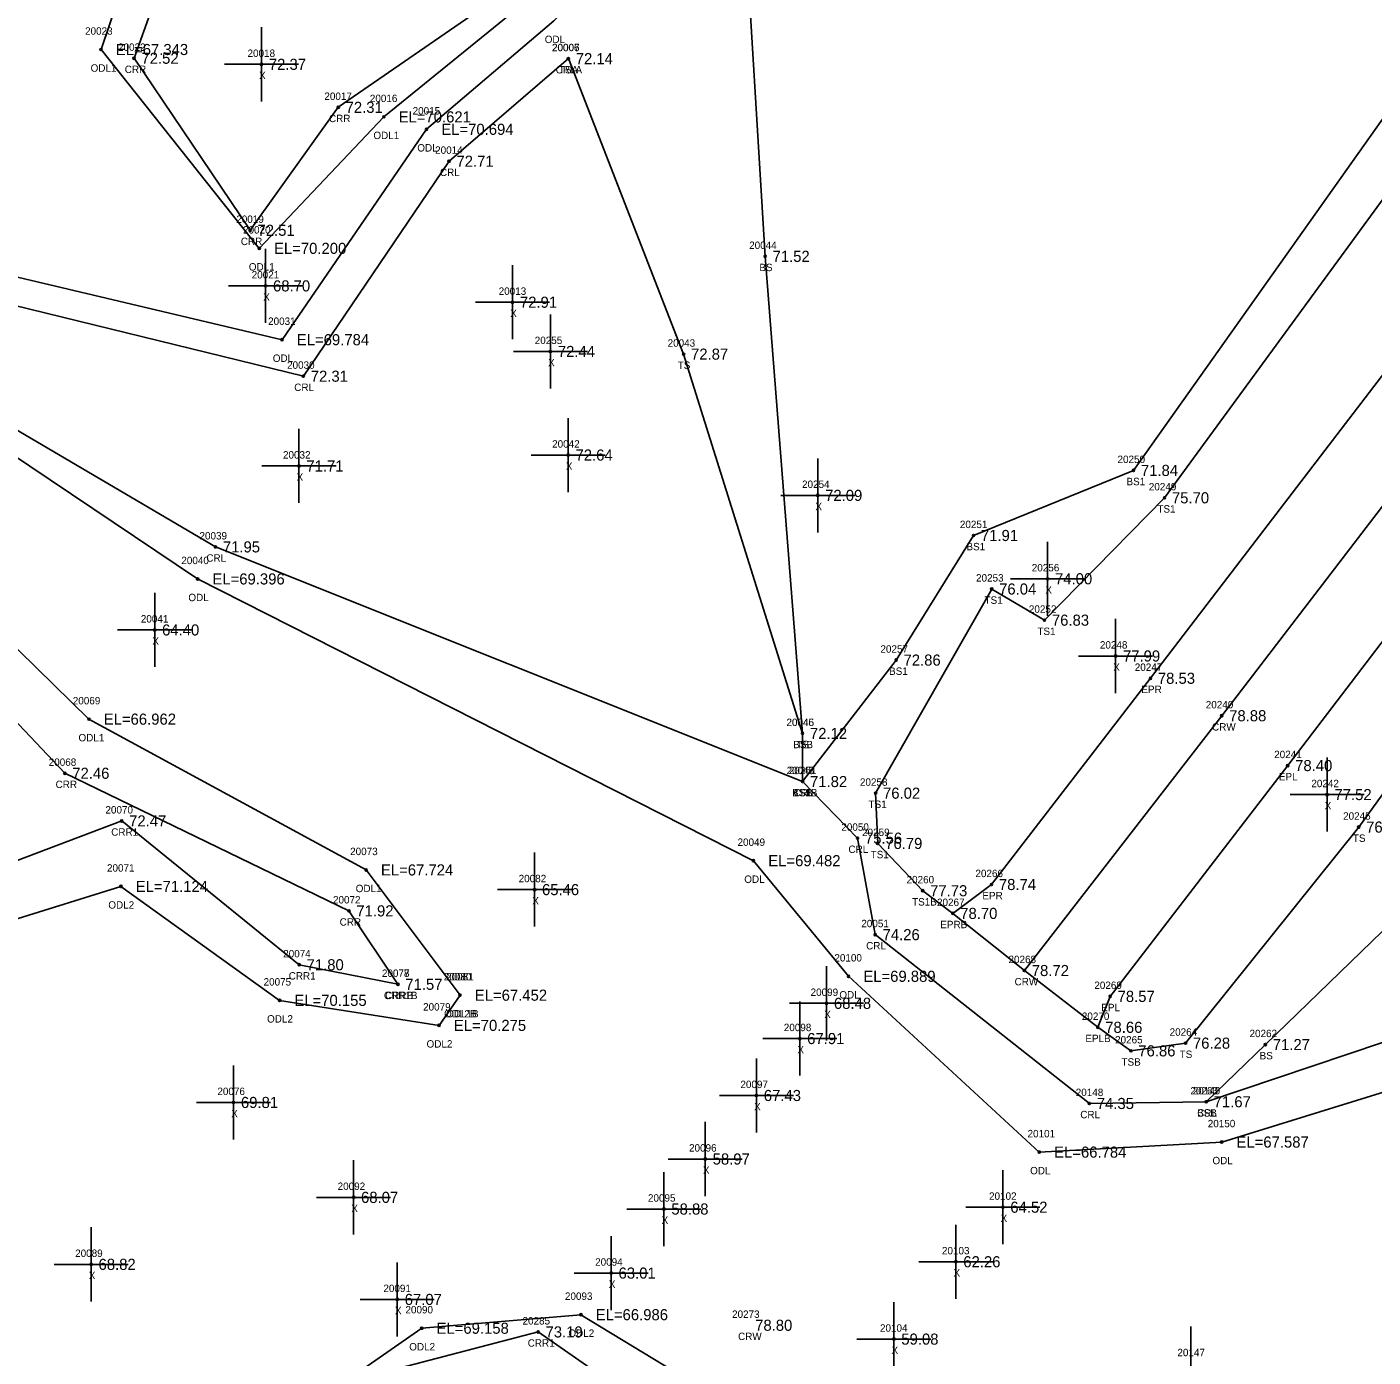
# Model space of a CAD drawing. Extents: x 2505300 to 2506184, y 912965 to 913825.
# Drawn here: x 2505689.1 to 2505870.9, y 913482.7 to 913662.4 of the extents above; entities that cross this region are included whole.
import ezdxf

# ---------------------------------------------------------------- set-up
doc = ezdxf.new("R2010")
doc.units = 0
for name, color, linetype in [('RD_DTM_BkLn1', 7, 'Continuous'), ('RD_DTM_BkLn2', 7, 'Continuous'), ('RD_DTM_BkLn_txCode', 7, 'Continuous'), ('RD_EX_H2O', 7, 'Continuous'), ('RD_EX_H2O_txCode', 7, 'Continuous'), ('RD_EX_Misc', 7, 'Continuous'), ('RD_EX_Misc_txCode', 7, 'Continuous'), ('RD_EX_Road', 7, 'Continuous'), ('RD_EX_Road_txCode', 7, 'Continuous'), ('RD_EX_TX_H2O_ELEV', 7, 'Continuous'), ('RD_EX_TX_Misc_ELEV', 7, 'Continuous'), ('RD_EX_TX_Road_ELEV', 7, 'Continuous'), ('RD_HC_Survey_ELEV', 7, 'Continuous'), ('RD_HC_Survey_txCode', 7, 'Continuous'), ('RD_SMD_Locator', 7, 'Continuous')]:
    doc.layers.add(name, color=color, linetype=linetype)

msp = doc.modelspace()

# ---------------------------------------------------------------- linework, layer by layer
at = {"layer": 'RD_DTM_BkLn1'}
for points in [[(2506032.26, 913807.16), (2505970.46, 913726.68), (2505911.98, 913649.53), (2505850.51, 913569.34), (2505823.85, 913534.92)], [(2505810.12, 913545.7), (2505814.19, 913542.64), (2505823.85, 913534.92), (2505833.77, 913527.25), (2505838.24, 913524.07)]]:
    msp.add_lwpolyline(points, dxfattribs=at)
at = {"layer": 'RD_DTM_BkLn2'}
for points in [[(2506003.2, 913816.23), (2505946.13, 913743.18), (2505885.35, 913668.51), (2505838.59, 913602.48), (2505816.98, 913593.69), (2505806.53, 913576.86), (2505793.9, 913560.45)], [(2506016.9, 913814.52), (2505950.1, 913739.73), (2505890.95, 913664.65), (2505842.78, 913598.78), (2505826.57, 913582.25), (2505819.44, 913586.46), (2505803.76, 913558.88), (2505804.05, 913552.09), (2505810.12, 913545.7)], [(2506050.33, 913797.99), (2506032.99, 913763.99), (2505986.64, 913715.48), (2505928.41, 913636.56), (2505869.01, 913554.3), (2505845.62, 913525.11), (2505838.24, 913524.07)], [(2506063.24, 913729.37), (2506038.62, 913753.69), (2505991.68, 913711.2), (2505934.4, 913631.37), (2505905.82, 913578.23), (2505899.85, 913572.14), (2505876.49, 913544.36), (2505856.4, 913524.92), (2505848.42, 913517.19)], [(2505785.34, 913689.17), (2505788.84, 913631.4), (2505793.89, 913566.95)], [(2505762.26, 913658.11), (2505777.83, 913618.19), (2505793.89, 913566.95), (2505793.9, 913560.45)]]:
    msp.add_lwpolyline(points, dxfattribs=at)
at = {"layer": 'RD_EX_H2O'}
for points in [[(2505785.34, 913689.17), (2505758.38, 913667.37), (2505737.34, 913650.24), (2505720.51, 913632.48), (2505699.15, 913659.34), (2505721.81, 913726.44)], [(2505757.9, 913670.02), (2505731.18, 913651.53), (2505719.28, 913634.92), (2505703.6, 913658.16), (2505725.09, 913718.19)], [(2505785.34, 913689.17), (2505760.31, 913663.21), (2505743.1, 913648.56), (2505723.59, 913620.14), (2505672.59, 913632.18), (2505661.09, 913622.14), (2505712.19, 913587.82), (2505787.26, 913549.76), (2505800.1, 913534.14), (2505825.87, 913510.39), (2505850.5, 913511.75), (2505883.26, 913521.88), (2505912.04, 913531.86), (2505948.81, 913534.96), (2505974.98, 913528.19), (2506003.87, 913517.71), (2506051.32, 913503.49), (2506114.3, 913484.75), (2506121.45, 913493.97), (2506156, 913550.08)], [(2505762.26, 913658.11), (2505746.15, 913644.25), (2505726.47, 913615.21), (2505674.21, 913628.01), (2505666.25, 913620.58), (2505714.6, 913592.15), (2505793.9, 913560.45), (2505801.32, 913552.8), (2505803.7, 913539.77), (2505832.63, 913516.96), (2505848.42, 913517.19), (2505881.86, 913528.44), (2505910.2, 913538.78), (2505939.3, 913544.45), (2505946.25, 913542.54), (2505974.65, 913535.18), (2506004.11, 913524.7), (2506052.03, 913515.47), (2506115.49, 913494.68), (2506138.05, 913548.89)], [(2505582.66, 913526.35), (2505594.25, 913570.52), (2505642.43, 913614.24), (2505650.18, 913615.25), (2505697.51, 913568.88), (2505734.95, 913548.51), (2505747.63, 913531.59)], [(2505594.65, 913525.76), (2505599.08, 913569.22), (2505647.5, 913611.03), (2505694.26, 913561.57), (2505732.63, 913542.98), (2505739.24, 913533.06)], [(2505594.65, 913525.76), (2505643.36, 913532.93), (2505701.94, 913555.13), (2505725.91, 913535.7), (2505739.24, 913533.06)], [(2505582.66, 913526.35), (2505594.35, 913519.76), (2505642.96, 913527.95), (2505701.83, 913546.28), (2505723.26, 913530.89), (2505744.8, 913527.51), (2505747.63, 913531.59)], [(2505660.9, 913411.21), (2505684.62, 913438.72), (2505715.28, 913467.7), (2505742.46, 913486.6), (2505763.96, 913488.43), (2505794.61, 913469.83), (2505812.57, 913467.2), (2505833.64, 913450.28), (2505872.88, 913457.34), (2505893.17, 913479.86), (2505942.46, 913480.08), (2505995.98, 913475.04), (2506045.33, 913460.93), (2506077.87, 913439.29), (2506087.99, 913429.78), (2506108.19, 913381.27)], [(2505789.47, 913464.31), (2505758.18, 913486.1), (2505736.66, 913480.49), (2505719.32, 913463.86), (2505699.9, 913439.21), (2505669.03, 913402.75), (2505628.5, 913357.9), (2505593, 913316.39), (2505556.58, 913279.8), (2505487.72, 913211.38), (2505413.81, 913149.81), (2505341.31, 913072.1)]]:
    msp.add_lwpolyline(points, dxfattribs=at)
at = {"layer": 'RD_EX_Misc'}
for p, q in [((2505720.81, 913652.34), (2505720.81, 913662.34)), ((2505715.81, 913657.34), (2505725.81, 913657.34)), ((2505721.37, 913622.41), (2505721.37, 913632.41)), ((2505754.72, 913620.2), (2505754.72, 913630.2)), ((2505716.37, 913627.41), (2505726.37, 913627.41)), ((2505749.72, 913625.2), (2505759.72, 913625.2)), ((2505759.84, 913613.55), (2505759.84, 913623.55)), ((2505754.84, 913618.55), (2505764.84, 913618.55)), ((2505762.23, 913599.56), (2505762.23, 913609.56)), ((2505725.88, 913598.08), (2505725.88, 913608.08)), ((2505757.23, 913604.56), (2505767.23, 913604.56)), ((2505795.94, 913594.11), (2505795.94, 913604.11)), ((2505720.88, 913603.08), (2505730.88, 913603.08)), ((2505790.94, 913599.11), (2505800.94, 913599.11)), ((2505826.99, 913582.84), (2505826.99, 913592.84)), ((2505821.99, 913587.84), (2505831.99, 913587.84)), ((2505706.39, 913575.93), (2505706.39, 913585.93)), ((2505836.17, 913572.41), (2505836.17, 913582.41)), ((2505701.39, 913580.93), (2505711.39, 913580.93)), ((2505831.17, 913577.41), (2505841.17, 913577.41)), ((2505864.73, 913553.69), (2505864.73, 913563.69)), ((2505859.73, 913558.69), (2505869.73, 913558.69)), ((2505757.7, 913540.85), (2505757.7, 913550.85)), ((2505752.7, 913545.85), (2505762.7, 913545.85)), ((2505797.13, 913525.49), (2505797.13, 913535.49)), ((2505792.13, 913530.49), (2505802.13, 913530.49)), ((2505793.52, 913520.73), (2505793.52, 913530.73)), ((2505788.52, 913525.73), (2505798.52, 913525.73)), ((2505717.04, 913512.1), (2505717.04, 913522.1)), ((2505787.66, 913513.04), (2505787.66, 913523.04)), ((2505712.04, 913517.1), (2505722.04, 913517.1)), ((2505782.66, 913518.04), (2505792.66, 913518.04)), ((2505780.75, 913504.46), (2505780.75, 913514.46)), ((2505733.26, 913499.28), (2505733.26, 913509.28)), ((2505775.75, 913509.46), (2505785.75, 913509.46)), ((2505775.17, 913497.7), (2505775.17, 913507.7)), ((2505820.95, 913497.95), (2505820.95, 913507.95)), ((2505728.26, 913504.28), (2505738.26, 913504.28)), ((2505770.17, 913502.7), (2505780.17, 913502.7)), ((2505815.95, 913502.95), (2505825.95, 913502.95)), ((2505697.81, 913490.23), (2505697.81, 913500.23)), ((2505814.6, 913490.58), (2505814.6, 913500.58)), ((2505768.04, 913489.05), (2505768.04, 913499.05)), ((2505692.81, 913495.23), (2505702.81, 913495.23)), ((2505739.16, 913485.49), (2505739.16, 913495.49)), ((2505809.6, 913495.58), (2505819.6, 913495.58)), ((2505763.04, 913494.05), (2505773.04, 913494.05)), ((2505734.16, 913490.49), (2505744.16, 913490.49)), ((2505806.23, 913480.13), (2505806.23, 913490.13)), ((2505846.35, 913476.82), (2505846.35, 913486.82)), ((2505801.23, 913485.13), (2505811.23, 913485.13))]:
    msp.add_line(p, q, dxfattribs=at)
at = {"layer": 'RD_EX_Road'}
for points in [[(2506024.03, 913813.1), (2505962.01, 913732.06), (2505903.3, 913655.93), (2505840.88, 913574.4), (2505819.41, 913546.54), (2505814.19, 913542.64)], [(2506040.71, 913800.23), (2505979.73, 913720.47), (2505920.44, 913642.61), (2505859.42, 913562.61), (2505835.44, 913531.43), (2505833.77, 913527.25)]]:
    msp.add_lwpolyline(points, dxfattribs=at)
at = {"layer": 'RD_SMD_Locator'}
for centre in [(2505699.15, 913659.34), (2505703.6, 913658.16), (2505720.81, 913657.34), (2505762.26, 913658.11), (2505762.26, 913658.11), (2505731.18, 913651.53), (2505737.34, 913650.24), (2505743.1, 913648.56), (2505746.15, 913644.25), (2505719.28, 913634.92), (2505720.51, 913632.48), (2505788.84, 913631.4), (2505721.37, 913627.41), (2505754.72, 913625.2), (2505723.59, 913620.14), (2505759.84, 913618.55), (2505777.83, 913618.19), (2505726.47, 913615.21), (2505762.23, 913604.56), (2505725.88, 913603.08), (2505838.59, 913602.48), (2505795.94, 913599.11), (2505842.78, 913598.78), (2505816.98, 913593.69), (2505714.6, 913592.15), (2505712.19, 913587.82), (2505826.99, 913587.84), (2505819.44, 913586.46), (2505826.57, 913582.25), (2505706.39, 913580.93), (2505806.53, 913576.86), (2505836.17, 913577.41), (2505840.88, 913574.4), (2505850.51, 913569.34), (2505697.51, 913568.88), (2505793.89, 913566.95), (2505793.89, 913566.95), (2505859.42, 913562.61), (2505694.26, 913561.57), (2505793.9, 913560.45), (2505793.9, 913560.45), (2505793.9, 913560.45), (2505803.76, 913558.88), (2505864.73, 913558.69), (2505701.94, 913555.13), (2505801.32, 913552.8), (2505869.01, 913554.3), (2505804.05, 913552.09), (2505787.26, 913549.76), (2505734.95, 913548.51), (2505701.83, 913546.28), (2505757.7, 913545.85), (2505810.12, 913545.7), (2505819.41, 913546.54), (2505732.63, 913542.98), (2505814.19, 913542.64), (2505803.7, 913539.77), (2505725.91, 913535.7), (2505823.85, 913534.92), (2505739.24, 913533.06), (2505739.24, 913533.06), (2505800.1, 913534.14), (2505747.63, 913531.59), (2505747.63, 913531.59), (2505835.44, 913531.43), (2505723.26, 913530.89), (2505797.13, 913530.49), (2505744.8, 913527.51), (2505793.52, 913525.73), (2505833.77, 913527.25), (2505838.24, 913524.07), (2505845.62, 913525.11), (2505856.4, 913524.92), (2505717.04, 913517.1), (2505787.66, 913518.04), (2505832.63, 913516.96), (2505848.42, 913517.19), (2505848.42, 913517.19), (2505850.5, 913511.75), (2505780.75, 913509.46), (2505825.87, 913510.39), (2505733.26, 913504.28), (2505775.17, 913502.7), (2505820.95, 913502.95), (2505697.81, 913495.23), (2505814.6, 913495.58), (2505768.04, 913494.05), (2505739.16, 913490.49), (2505763.96, 913488.43), (2505742.46, 913486.6), (2505758.18, 913486.1), (2505806.23, 913485.13)]:
    msp.add_circle(centre, 0.15, dxfattribs=at)

# ---------------------------------------------------------------- texts
at = {"layer": 'RD_DTM_BkLn_txCode'}
for s, p in [('20007', (2505760.07, 913659.11)), ('TSA', (2505760.98, 913656.11)), ('20044', (2505786.68, 913632.4)), ('BS', (2505788.06, 913629.4)), ('20043', (2505775.67, 913619.19)), ('TS', (2505777.03, 913616.19)), ('20250', (2505836.43, 913603.48)), ('BS1', (2505837.64, 913600.48)), ('20249', (2505840.66, 913599.78)), ('TS1', (2505841.82, 913596.78)), ('20251', (2505815.14, 913594.69)), ('BS1', (2505816.03, 913591.69)), ('20253', (2505817.32, 913587.46)), ('TS1', (2505818.47, 913584.46)), ('20252', (2505824.46, 913583.25)), ('TS1', (2505825.61, 913580.25)), ('20257', (2505804.41, 913577.86)), ('BS1', (2505805.58, 913574.86)), ('20046', (2505791.71, 913567.95)), ('20045', (2505791.73, 913567.95)), ('BSB', (2505792.63, 913564.95)), ('TS', (2505793.09, 913564.95)), ('20047', (2505791.74, 913561.45)), ('20261', (2505792.04, 913561.45)), ('20258', (2505801.64, 913559.88)), ('BS1B', (2505792.48, 913558.45)), ('TSB', (2505792.63, 913558.45)), ('TS1', (2505802.8, 913556.88)), ('20245', (2505866.9, 913555.3)), ('20259', (2505801.93, 913553.09)), ('TS', (2505868.22, 913552.3)), ('TS1', (2505803.09, 913550.09)), ('20260', (2505807.94, 913546.7)), ('TS1B', (2505808.68, 913543.7)), ('20265', (2505836.1, 913525.07)), ('20264', (2505843.47, 913526.11)), ('20262', (2505854.26, 913525.92)), ('TS', (2505844.82, 913523.11)), ('BS', (2505855.62, 913522.92)), ('TSB', (2505836.97, 913522.07)), ('20263', (2505846.28, 913518.19)), ('BSB', (2505847.17, 913515.19))]:
    msp.add_text(s, height=1, dxfattribs=at).set_placement(p)
at = {"layer": 'RD_EX_H2O_txCode'}
for s, p in [('20023', (2505696.99, 913661.34)), ('20022', (2505701.44, 913659.16)), ('ODL', (2505759.07, 913660.21)), ('20006', (2505760.04, 913659.11)), ('ODL1', (2505697.74, 913656.34)), ('CRR', (2505702.35, 913656.16)), ('CRLA', (2505760.55, 913656.11)), ('20017', (2505729.31, 913652.53)), ('20016', (2505735.45, 913652.24)), ('20015', (2505741.23, 913650.56)), ('CRR', (2505729.93, 913649.53)), ('ODL1', (2505735.93, 913647.24)), ('ODL', (2505741.86, 913645.56)), ('20014', (2505744.27, 913645.25)), ('CRL', (2505744.92, 913642.25)), ('20019', (2505717.41, 913635.92)), ('20020', (2505718.32, 913634.48)), ('CRR', (2505718.03, 913632.92)), ('ODL1', (2505719.1, 913629.48)), ('20031', (2505721.71, 913622.14)), ('ODL', (2505722.34, 913617.14)), ('20030', (2505724.27, 913616.21)), ('CRL', (2505725.24, 913613.21)), ('20039', (2505712.44, 913593.15)), ('CRL', (2505713.37, 913590.15)), ('20040', (2505709.99, 913589.82)), ('ODL', (2505710.94, 913584.82)), ('20069', (2505695.33, 913570.88)), ('ODL1', (2505696.1, 913565.88)), ('20068', (2505692.08, 913562.57)), ('20048', (2505791.74, 913561.45)), ('CRR', (2505693.01, 913559.57)), ('CRL', (2505792.67, 913558.45)), ('20070', (2505699.74, 913556.13)), ('20050', (2505799.13, 913553.8)), ('CRR1', (2505700.52, 913553.13)), ('20073', (2505732.79, 913550.51)), ('20049', (2505785.11, 913551.76)), ('CRL', (2505800.09, 913550.8)), ('20071', (2505699.95, 913548.28)), ('ODL', (2505786.02, 913546.76)), ('ODL1', (2505733.54, 913545.51)), ('ODL2', (2505700.13, 913543.28)), ('20072', (2505730.47, 913543.98)), ('CRR', (2505731.37, 913540.98)), ('20051', (2505801.83, 913540.77)), ('CRL', (2505802.48, 913537.77)), ('20074', (2505723.75, 913536.7)), ('20100', (2505798.19, 913536.14)), ('20077', (2505737.08, 913534.06)), ('20078', (2505737.08, 913534.06)), ('20075', (2505721.1, 913532.89)), ('CRR1', (2505724.49, 913533.7)), ('20080', (2505745.44, 913533.59)), ('20081', (2505745.76, 913533.59)), ('CRR1B', (2505737.35, 913531.06)), ('CRRB', (2505737.52, 913531.06)), ('ODL', (2505798.86, 913531.14)), ('20079', (2505742.64, 913529.51)), ('ODL2B', (2505745.47, 913528.59)), ('ODL1B', (2505745.75, 913528.59)), ('ODL2', (2505721.57, 913527.89)), ('ODL2', (2505743.11, 913524.51)), ('20148', (2505830.79, 913517.96)), ('20149', (2505846.59, 913518.19)), ('CRL', (2505831.4, 913514.96)), ('CRL', (2505847.2, 913515.19)), ('20150', (2505848.62, 913513.75)), ('20101', (2505824.28, 913512.39)), ('ODL', (2505849.25, 913508.75)), ('ODL', (2505824.63, 913507.39)), ('20093', (2505761.8, 913490.43)), ('20090', (2505740.26, 913488.6)), ('20285', (2505756.07, 913487.1)), ('ODL2', (2505762.26, 913485.43)), ('ODL2', (2505740.77, 913483.6)), ('CRR1', (2505756.77, 913484.1))]:
    msp.add_text(s, height=1, dxfattribs=at).set_placement(p)
at = {"layer": 'RD_EX_Misc_txCode'}
for s, p in [('20018', (2505718.93, 913658.34)), ('X', (2505720.49, 913655.34)), ('20021', (2505719.49, 913628.41)), ('X', (2505721.05, 913625.41)), ('20013', (2505752.85, 913626.2)), ('X', (2505754.41, 913623.2)), ('20255', (2505757.72, 913619.55)), ('X', (2505759.53, 913616.55)), ('20042', (2505760.07, 913605.56)), ('20032', (2505723.72, 913604.08)), ('X', (2505725.56, 913601.08)), ('X', (2505761.92, 913602.56)), ('20254', (2505793.82, 913600.11)), ('X', (2505795.63, 913597.11)), ('20256', (2505824.85, 913588.84)), ('X', (2505826.68, 913585.84)), ('20041', (2505704.52, 913581.93)), ('X', (2505706.07, 913578.93)), ('20248', (2505834.05, 913578.41)), ('X', (2505835.85, 913575.41)), ('20242', (2505862.61, 913559.69)), ('X', (2505864.41, 913556.69)), ('20082', (2505755.55, 913546.85)), ('X', (2505757.39, 913543.85)), ('20099', (2505794.98, 913531.49)), ('X', (2505796.82, 913528.49)), ('20098', (2505791.36, 913526.73)), ('X', (2505793.2, 913523.73)), ('20076', (2505714.86, 913518.1)), ('20097', (2505785.5, 913519.04)), ('X', (2505787.35, 913516.04)), ('X', (2505716.73, 913515.1)), ('20096', (2505778.56, 913510.46)), ('X', (2505780.43, 913507.46)), ('20092', (2505731.1, 913505.28)), ('20095', (2505773.01, 913503.7)), ('20102', (2505819.08, 913503.95)), ('X', (2505732.95, 913502.28)), ('X', (2505774.86, 913500.7)), ('X', (2505820.64, 913500.95)), ('20089', (2505695.65, 913496.23)), ('20103', (2505812.72, 913496.58)), ('20094', (2505765.88, 913495.05)), ('X', (2505697.49, 913493.23)), ('X', (2505767.72, 913492.05)), ('X', (2505814.28, 913493.58)), ('20091', (2505737.28, 913491.49)), ('X', (2505738.84, 913488.49)), ('20104', (2505804.35, 913486.13)), ('X', (2505805.91, 913483.13)), ('20147', (2505844.52, 913482.82))]:
    msp.add_text(s, height=1, dxfattribs=at).set_placement(p)
at = {"layer": 'RD_EX_Road_txCode'}
for s, p in [('20247', (2505838.76, 913575.4)), ('EPR', (2505839.65, 913572.4)), ('20241', (2505857.59, 913563.61)), ('EPL', (2505858.22, 913560.61)), ('20266', (2505817.24, 913547.54)), ('20267', (2505812.05, 913543.64)), ('EPR', (2505818.18, 913544.54)), ('EPRB', (2505812.49, 913540.64)), ('20269', (2505833.3, 913532.43)), ('20270', (2505831.61, 913528.25)), ('EPL', (2505834.24, 913529.43)), ('EPLB', (2505832.09, 913525.25))]:
    msp.add_text(s, height=1, dxfattribs=at).set_placement(p)
at = {"layer": 'RD_EX_TX_H2O_ELEV'}
for s, p in [('EL=67.343', (2505701.15, 913658.59)), ('72.52', (2505704.6, 913657.41)), ('72.14', (2505763.26, 913657.36)), ('72.31', (2505732.18, 913650.78)), ('EL=70.621', (2505739.34, 913649.49)), ('EL=70.694', (2505745.1, 913647.81)), ('72.71', (2505747.15, 913643.5)), ('72.51', (2505720.28, 913634.17)), ('EL=70.200', (2505722.51, 913631.73)), ('EL=69.784', (2505725.59, 913619.39)), ('72.31', (2505727.47, 913614.46)), ('71.95', (2505715.6, 913591.4)), ('EL=69.396', (2505714.19, 913587.07)), ('EL=66.962', (2505699.51, 913568.13)), ('72.46', (2505695.26, 913560.82)), ('71.82', (2505794.9, 913559.7)), ('72.47', (2505702.94, 913554.38)), ('75.56', (2505802.32, 913552.05)), ('EL=67.724', (2505736.95, 913547.76)), ('EL=69.482', (2505789.26, 913549.01)), ('EL=71.124', (2505703.83, 913545.53)), ('71.92', (2505733.63, 913542.23)), ('74.26', (2505804.7, 913539.02)), ('71.80', (2505726.91, 913534.95)), ('EL=69.889', (2505802.1, 913533.39)), ('71.57', (2505740.24, 913532.31)), ('71.57', (2505740.24, 913532.31)), ('EL=70.155', (2505725.26, 913530.14)), ('EL=67.452', (2505749.63, 913530.84)), ('EL=67.452', (2505749.63, 913530.84)), ('EL=70.275', (2505746.8, 913526.76)), ('74.35', (2505833.63, 913516.21)), ('71.67', (2505849.42, 913516.44)), ('EL=66.784', (2505827.87, 913509.64)), ('EL=67.587', (2505852.5, 913511)), ('EL=66.986', (2505765.96, 913487.68)), ('EL=69.158', (2505744.46, 913485.85)), ('73.19', (2505759.18, 913485.35))]:
    msp.add_text(s, height=1.5, dxfattribs=at).set_placement(p)
at = {"layer": 'RD_EX_TX_Misc_ELEV'}
for s, p in [('72.14', (2505763.26, 913657.36)), ('72.37', (2505721.81, 913656.59)), ('71.52', (2505789.84, 913630.65)), ('68.70', (2505722.37, 913626.66)), ('72.91', (2505755.72, 913624.45)), ('72.44', (2505760.84, 913617.8)), ('72.87', (2505778.83, 913617.44)), ('71.71', (2505726.88, 913602.33)), ('72.64', (2505763.23, 913603.81)), ('71.84', (2505839.59, 913601.73)), ('72.09', (2505796.94, 913598.36)), ('75.70', (2505843.78, 913598.03)), ('71.91', (2505817.98, 913592.94)), ('74.00', (2505827.99, 913587.09)), ('76.04', (2505820.44, 913585.71)), ('76.83', (2505827.57, 913581.5)), ('64.40', (2505707.39, 913580.18)), ('72.86', (2505807.53, 913576.11)), ('77.99', (2505837.17, 913576.66)), ('72.12', (2505794.89, 913566.2)), ('72.12', (2505794.89, 913566.2)), ('71.82', (2505794.9, 913559.7)), ('71.82', (2505794.9, 913559.7)), ('76.02', (2505804.76, 913558.13)), ('77.52', (2505865.73, 913557.94)), ('76.91', (2505870.01, 913553.55)), ('76.79', (2505805.05, 913551.34)), ('65.46', (2505758.7, 913545.1)), ('77.73', (2505811.12, 913544.95)), ('68.48', (2505798.13, 913529.74)), ('67.91', (2505794.52, 913524.98)), ('76.28', (2505846.62, 913524.36)), ('71.27', (2505857.4, 913524.17)), ('76.86', (2505839.24, 913523.32)), ('67.43', (2505788.66, 913517.29)), ('69.81', (2505718.04, 913516.35)), ('71.67', (2505849.42, 913516.44)), ('58.97', (2505781.75, 913508.71)), ('68.07', (2505734.26, 913503.53)), ('58.88', (2505776.17, 913501.95)), ('64.52', (2505821.95, 913502.2)), ('68.82', (2505698.81, 913494.48)), ('63.01', (2505769.04, 913493.3)), ('62.26', (2505815.6, 913494.83)), ('67.07', (2505740.16, 913489.74)), ('59.08', (2505807.23, 913484.38))]:
    msp.add_text(s, height=1.5, dxfattribs=at).set_placement(p)
at = {"layer": 'RD_EX_TX_Road_ELEV'}
for s, p in [('78.53', (2505841.88, 913573.65)), ('78.40', (2505860.42, 913561.86)), ('78.74', (2505820.41, 913545.79)), ('78.70', (2505815.19, 913541.89)), ('78.57', (2505836.44, 913530.68)), ('78.66', (2505834.77, 913526.5))]:
    msp.add_text(s, height=1.5, dxfattribs=at).set_placement(p)
at = {"layer": 'RD_HC_Survey_ELEV'}
for s, p in [('78.88', (2505851.51, 913568.59)), ('78.72', (2505824.85, 913534.17)), ('78.80', (2505787.49, 913486.25))]:
    msp.add_text(s, height=1.5, dxfattribs=at).set_placement(p)
at = {"layer": 'RD_HC_Survey_txCode'}
for s, p in [('20240', (2505848.35, 913570.34)), ('CRW', (2505849.2, 913567.34)), ('20268', (2505821.71, 913535.92)), ('CRW', (2505822.53, 913532.92)), ('20273', (2505784.37, 913488)), ('CRW', (2505785.18, 913485))]:
    msp.add_text(s, height=1, dxfattribs=at).set_placement(p)

doc.saveas('drawing.dxf')
